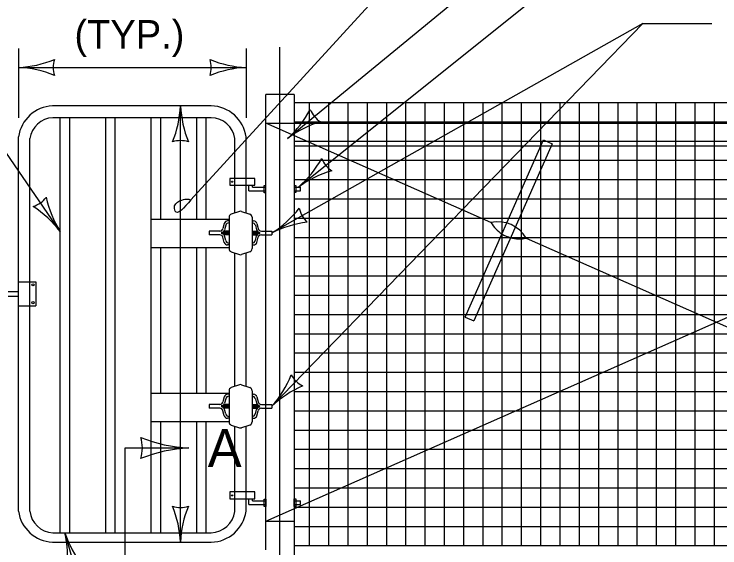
# Model space of a CAD drawing. Extents: x 49991.4 to 50021, y 49987.6 to 50011.4.
# Drawn here: x 50002.451 to 50003.939, y 49989.872 to 49990.998 of the extents above; entities that cross this region are included whole.
import ezdxf

# ---------------------------------------------------------------- set-up
doc = ezdxf.new("R2010")
doc.units = 0
for name, color, linetype in [('Level 1', 7, 'Continuous'), ('Level 2', 7, 'Continuous'), ('Level 3', 7, 'Continuous'), ('Level 4', 7, 'Continuous'), ('Level 5', 7, 'Continuous'), ('Level 6', 7, 'Continuous')]:
    doc.layers.add(name, color=color, linetype=linetype)

msp = doc.modelspace()

# ---------------------------------------------------------------- linework, layer by layer
at = {"layer": 'Level 1'}
for p, q in [((50003.0415, 49990.8281), (50002.9815, 49990.8281)), ((50002.9815, 49990.5402), (50002.9815, 49990.8281)), ((50003.0415, 49990.8281), (50003.0415, 49989.8078)), ((50004.8216, 49990.8107), (50003.0415, 49990.8107)), ((50003.074, 49989.8759), (50003.074, 49990.8107)), ((50003.1146, 49989.8759), (50003.1146, 49990.8107)), ((50003.1553, 49989.8759), (50003.1553, 49990.8107)), ((50003.1959, 49989.8759), (50003.1959, 49990.8107)), ((50003.2366, 49989.8759), (50003.2366, 49990.8107)), ((50003.2772, 49989.8759), (50003.2772, 49990.8107)), ((50003.3178, 49989.8759), (50003.3178, 49990.8107)), ((50003.3585, 49989.8759), (50003.3585, 49990.8107)), ((50003.3991, 49989.8759), (50003.3991, 49990.8107)), ((50003.4398, 49989.8759), (50003.4398, 49990.8107)), ((50003.4804, 49989.8759), (50003.4804, 49990.8107)), ((50003.5211, 49989.8759), (50003.5211, 49990.8107)), ((50003.5617, 49989.8759), (50003.5617, 49990.8107)), ((50003.6023, 49989.8759), (50003.6023, 49990.8107)), ((50003.643, 49989.8759), (50003.643, 49990.8107)), ((50003.6836, 49989.8759), (50003.6836, 49990.8107)), ((50003.7243, 49989.8759), (50003.7243, 49990.8107)), ((50003.7649, 49989.8759), (50003.7649, 49990.8107)), ((50003.8055, 49989.8759), (50003.8055, 49990.8107)), ((50003.8462, 49989.8759), (50003.8462, 49990.8107)), ((50003.8868, 49989.8759), (50003.8868, 49990.8107)), ((50003.9275, 49989.8759), (50003.9275, 49990.8107)), ((50002.8667, 49990.8044), (50002.532, 49990.8044)), ((50002.8669, 49990.7794), (50002.5324, 49990.7794)), ((50002.5483, 49989.9038), (50002.5483, 49990.7794)), ((50002.5683, 49989.9038), (50002.5683, 49990.7794)), ((50002.6443, 49989.9038), (50002.6443, 49990.7794)), ((50002.6643, 49989.9038), (50002.6643, 49990.7794)), ((50002.7403, 49989.9038), (50002.7403, 49990.7794)), ((50002.7603, 49990.5652), (50002.7603, 49990.7794)), ((50002.8363, 49990.5652), (50002.8363, 49990.7794)), ((50002.8563, 49990.5652), (50002.8563, 49990.7794)), ((50002.9815, 49990.768), (50004.8216, 49990.768)), ((50003.4565, 49990.5582), (50002.9815, 49990.768)), ((50004.8216, 49990.77), (50003.0415, 49990.77)), ((50002.4602, 49989.9493), (50002.4602, 49990.7389)), ((50002.4842, 49989.9493), (50002.4842, 49990.7354)), ((50002.9162, 49990.5782), (50002.9162, 49990.7353)), ((50002.9402, 49990.5784), (50002.9402, 49990.7388)), ((50003.402, 49990.3588), (50003.5671, 49990.7324)), ((50003.5671, 49990.7324), (50003.5854, 49990.7243)), ((50004.8216, 49990.7294), (50003.0415, 49990.7294)), ((50003.0415, 49990.7201), (50004.8216, 49990.7201)), ((50003.5854, 49990.7243), (50003.4202, 49990.3507)), ((50004.8216, 49990.6888), (50003.0415, 49990.6888)), ((50002.9057, 49990.6514), (50002.9057, 49990.6367)), ((50002.9588, 49990.6514), (50002.9057, 49990.6514)), ((50002.9588, 49990.6367), (50002.9588, 49990.6514)), ((50004.8216, 49990.6481), (50003.0415, 49990.6481)), ((50002.9057, 49990.6367), (50002.9588, 49990.6367)), ((50002.9461, 49990.6253), (50002.9461, 49990.6367)), ((50002.9537, 49990.6328), (50002.9537, 49990.6367)), ((50002.9537, 49990.6328), (50002.9815, 49990.6328)), ((50002.978, 49990.621), (50002.978, 49990.6365)), ((50002.978, 49990.6365), (50002.9815, 49990.6365)), ((50003.0415, 49990.6366), (50003.045, 49990.6366)), ((50003.0416, 49990.6328), (50003.055, 49990.6328)), ((50003.045, 49990.6366), (50003.045, 49990.6212)), ((50003.055, 49990.6253), (50003.055, 49990.6328)), ((50002.9461, 49990.6253), (50002.9815, 49990.6253)), ((50002.9815, 49990.621), (50002.978, 49990.621)), ((50003.0415, 49990.6253), (50003.055, 49990.6253)), ((50003.045, 49990.6212), (50003.0415, 49990.6212)), ((50004.8216, 49990.6075), (50003.0415, 49990.6075)), ((50002.9042, 49990.5692), (50002.9042, 49990.5031)), ((50002.9263, 49990.5815), (50002.909, 49990.5758)), ((50002.9307, 49990.5815), (50002.948, 49990.5758)), ((50002.9528, 49990.5692), (50002.9528, 49990.5031)), ((50002.7403, 49990.5652), (50002.9042, 49990.5652)), ((50002.8942, 49990.5563), (50002.8913, 49990.5453)), ((50002.9042, 49990.5615), (50002.901, 49990.5615)), ((50002.9042, 49990.5575), (50002.904, 49990.5575)), ((50002.9528, 49990.5615), (50002.956, 49990.5615)), ((50002.9528, 49990.5575), (50002.9529, 49990.5575)), ((50002.9628, 49990.5563), (50002.9657, 49990.5453)), ((50004.8216, 49990.5668), (50003.0415, 49990.5668)), ((50002.8625, 49990.5402), (50002.8625, 49990.5322)), ((50002.8845, 49990.5402), (50002.8625, 49990.5402)), ((50002.9042, 49990.5402), (50002.8935, 49990.5402)), ((50002.8973, 49990.5523), (50002.8947, 49990.5425)), ((50002.9528, 49990.5402), (50002.9635, 49990.5402)), ((50002.9597, 49990.5523), (50002.9623, 49990.5425)), ((50002.9724, 49990.5402), (50002.9945, 49990.5402)), ((50002.9815, 49990.5322), (50002.9815, 49990.5402)), ((50002.9945, 49990.5402), (50002.9945, 49990.5322)), ((50002.8845, 49990.5322), (50002.8625, 49990.5322)), ((50002.9042, 49990.5374), (50002.8879, 49990.5374)), ((50002.9042, 49990.535), (50002.8879, 49990.535)), ((50002.8942, 49990.516), (50002.8913, 49990.527)), ((50002.9042, 49990.5322), (50002.8935, 49990.5322)), ((50002.8973, 49990.52), (50002.8947, 49990.5298)), ((50002.9528, 49990.5374), (50002.9691, 49990.5374)), ((50002.9528, 49990.535), (50002.9691, 49990.535)), ((50002.9528, 49990.5322), (50002.9635, 49990.5322)), ((50002.9597, 49990.52), (50002.9623, 49990.5298)), ((50002.9628, 49990.516), (50002.9657, 49990.527)), ((50002.9724, 49990.5322), (50002.9945, 49990.5322)), ((50002.9815, 49990.1745), (50002.9815, 49990.5322)), ((50002.9815, 49989.928), (50004.3322, 49990.5251)), ((50004.8216, 49990.5262), (50003.0415, 49990.5262)), ((50003.5309, 49990.5253), (50004.8816, 49989.9281)), ((50002.9042, 49990.5109), (50002.901, 49990.5109)), ((50002.9042, 49990.5149), (50002.904, 49990.5149)), ((50002.9528, 49990.5149), (50002.9529, 49990.5149)), ((50002.9528, 49990.5109), (50002.956, 49990.5109)), ((50002.7403, 49990.5052), (50002.9042, 49990.5052)), ((50002.7603, 49990.1982), (50002.7603, 49990.5052)), ((50002.8363, 49990.1982), (50002.8363, 49990.5052)), ((50002.8563, 49990.1982), (50002.8563, 49990.5052)), ((50002.909, 49990.4965), (50002.9263, 49990.4908)), ((50002.9162, 49990.2126), (50002.9162, 49990.4941)), ((50002.948, 49990.4965), (50002.9307, 49990.4908)), ((50002.9402, 49990.2127), (50002.9402, 49990.4939)), ((50004.8216, 49990.4855), (50003.0415, 49990.4855)), ((50004.8216, 49990.4449), (50003.0415, 49990.4449)), ((50002.4602, 49990.4332), (50002.4967, 49990.4332)), ((50002.4967, 49990.4332), (50002.4967, 49990.3824)), ((50002.4389, 49990.4128), (50002.4602, 49990.4128)), ((50002.4389, 49990.4028), (50002.4602, 49990.4028)), ((50004.8216, 49990.4043), (50003.0415, 49990.4043)), ((50002.4602, 49990.3824), (50002.4967, 49990.3824)), ((50004.8216, 49990.3636), (50003.0415, 49990.3636)), ((50003.402, 49990.3588), (50003.4202, 49990.3507)), ((50004.8216, 49990.323), (50003.0415, 49990.323)), ((50004.8216, 49990.2823), (50003.0415, 49990.2823)), ((50004.8216, 49990.2417), (50003.0415, 49990.2417)), ((50002.9263, 49990.2159), (50002.909, 49990.2102)), ((50002.9307, 49990.2159), (50002.948, 49990.2102)), ((50002.7403, 49990.1982), (50002.9042, 49990.1982)), ((50002.9042, 49990.2035), (50002.9042, 49990.1375)), ((50002.9528, 49990.2035), (50002.9528, 49990.1375)), ((50004.8216, 49990.201), (50003.0415, 49990.201)), ((50002.8942, 49990.1906), (50002.8913, 49990.1797)), ((50002.8973, 49990.1866), (50002.8947, 49990.1769)), ((50002.9042, 49990.1958), (50002.901, 49990.1958)), ((50002.9042, 49990.1918), (50002.904, 49990.1918)), ((50002.9528, 49990.1958), (50002.956, 49990.1958)), ((50002.9528, 49990.1918), (50002.9529, 49990.1918)), ((50002.9597, 49990.1866), (50002.9623, 49990.1769)), ((50002.9628, 49990.1906), (50002.9657, 49990.1797)), ((50002.8625, 49990.1745), (50002.8625, 49990.1665)), ((50002.8845, 49990.1745), (50002.8625, 49990.1745)), ((50002.9042, 49990.1717), (50002.8879, 49990.1717)), ((50002.9042, 49990.1693), (50002.8879, 49990.1693)), ((50002.9042, 49990.1745), (50002.8935, 49990.1745)), ((50002.9528, 49990.1745), (50002.9635, 49990.1745)), ((50002.9528, 49990.1717), (50002.9691, 49990.1717)), ((50002.9528, 49990.1693), (50002.9691, 49990.1693)), ((50002.9724, 49990.1745), (50002.9945, 49990.1745)), ((50002.9815, 49990.1665), (50002.9815, 49990.1745)), ((50002.9945, 49990.1745), (50002.9945, 49990.1665)), ((50002.8845, 49990.1665), (50002.8625, 49990.1665)), ((50002.8942, 49990.1504), (50002.8913, 49990.1613)), ((50002.9042, 49990.1665), (50002.8935, 49990.1665)), ((50002.8973, 49990.1544), (50002.8947, 49990.1641)), ((50002.9528, 49990.1665), (50002.9635, 49990.1665)), ((50002.9597, 49990.1544), (50002.9623, 49990.1641)), ((50002.9628, 49990.1504), (50002.9657, 49990.1613)), ((50002.9724, 49990.1665), (50002.9945, 49990.1665)), ((50002.9815, 49989.8678), (50002.9815, 49990.1665)), ((50004.8216, 49990.1604), (50003.0415, 49990.1604)), ((50002.7403, 49990.1382), (50002.9042, 49990.1382)), ((50002.7603, 49989.9038), (50002.7603, 49990.1382)), ((50002.8363, 49989.9038), (50002.8363, 49990.1382)), ((50002.8563, 49989.9038), (50002.8563, 49990.1382)), ((50002.9042, 49990.1452), (50002.901, 49990.1452)), ((50002.9042, 49990.1492), (50002.904, 49990.1492)), ((50002.9528, 49990.1492), (50002.9529, 49990.1492)), ((50002.9528, 49990.1452), (50002.956, 49990.1452)), ((50002.909, 49990.1308), (50002.9263, 49990.1251)), ((50002.9162, 49989.9488), (50002.9162, 49990.1284)), ((50002.948, 49990.1308), (50002.9307, 49990.1251)), ((50002.9402, 49989.9494), (50002.9402, 49990.1282)), ((50004.8216, 49990.1198), (50003.0415, 49990.1198)), ((50004.8216, 49990.0791), (50003.0415, 49990.0791)), ((50004.8216, 49990.0385), (50003.0415, 49990.0385)), ((50004.8216, 49989.9978), (50003.0415, 49989.9978)), ((50002.9461, 49989.9636), (50002.9461, 49989.9751)), ((50002.9537, 49989.9712), (50002.9537, 49989.9751)), ((50002.9461, 49989.9636), (50002.9815, 49989.9636)), ((50002.9537, 49989.9712), (50002.9815, 49989.9712)), ((50003.0415, 49989.9712), (50003.055, 49989.9712)), ((50003.0415, 49989.9636), (50003.055, 49989.9636)), ((50003.055, 49989.9636), (50003.055, 49989.9712)), ((50004.8216, 49989.9572), (50003.0415, 49989.9572)), ((50002.9815, 49989.928), (50003.0415, 49989.928)), ((50004.8216, 49989.9166), (50003.0415, 49989.9166)), ((50002.5324, 49989.9038), (50002.8667, 49989.9038)), ((50002.5319, 49989.8838), (50002.8667, 49989.8838)), ((50004.8216, 49989.8759), (50003.0415, 49989.8759))]:
    msp.add_line(p, q, dxfattribs=at)
for points in [[(50002.9588, 49989.9751), (50002.9588, 49989.9898), (50002.9057, 49989.9898), (50002.9057, 49989.9751)], [(50002.9815, 49989.9748), (50002.9815, 49989.9594), (50002.978, 49989.9594), (50002.978, 49989.9748)], [(50003.045, 49989.975), (50003.045, 49989.9595), (50003.0415, 49989.9595), (50003.0415, 49989.975)]]:
    msp.add_lwpolyline(points, close=True, dxfattribs=at)
for centre, radius in [((50002.9108, 49990.6443), 0.00125), ((50002.4909, 49990.4269), 0.00227), ((50002.4909, 49990.389), 0.00227), ((50002.9108, 49989.9827), 0.00125)]:
    msp.add_circle(centre, radius, dxfattribs=at)
for centre, radius, start, end in [((50002.5357, 49990.7283), 0.0762, 92.7377, 171.9677), ((50002.8647, 49990.7282), 0.0762, 8.0258, 88.4771), ((50002.5349, 49990.7282), 0.0512, 92.7386, 171.9742), ((50002.8655, 49990.7282), 0.0512, 8.0258, 88.4771), ((50002.9112, 49990.5692), 0.007, 108.219, 180), ((50002.9285, 49990.5749), 0.007, 71.7915, 108.219), ((50002.9458, 49990.5692), 0.007, 0, 71.7915), ((50002.901, 49990.5545), 0.007, 90, 165), ((50002.904, 49990.5505), 0.007, 88.8157, 165), ((50002.9529, 49990.5505), 0.007, 15, 90), ((50002.956, 49990.5545), 0.007, 15, 90), ((50003.4709, 49990.4903), 0.0694, 30.2241, 102.0148), ((50003.5164, 49990.5932), 0.0694, 210.2884, 237.9426), ((50002.8845, 49990.5472), 0.007, 270, 345), ((50002.8879, 49990.5444), 0.007, 270, 345), ((50002.9691, 49990.5444), 0.007, 195, 270), ((50002.9724, 49990.5472), 0.007, 195, 270), ((50002.8845, 49990.5252), 0.007, 15, 90), ((50002.8879, 49990.528), 0.007, 15, 90), ((50002.9691, 49990.528), 0.007, 90, 165), ((50002.9724, 49990.5252), 0.007, 90, 165), ((50003.5165, 49990.5931), 0.0694, 254.4342, 281.9719), ((50002.901, 49990.5179), 0.007, 195, 270), ((50002.904, 49990.5219), 0.007, 195, 271.1843), ((50002.9529, 49990.5219), 0.007, 270, 345), ((50002.956, 49990.5179), 0.007, 270, 345), ((50002.9112, 49990.5031), 0.007, 180, 251.781), ((50002.9458, 49990.5031), 0.007, 288.2085, 360), ((50002.9285, 49990.4974), 0.007, 251.781, 288.2085), ((50002.9285, 49990.2092), 0.007, 71.7915, 108.219), ((50002.9112, 49990.2035), 0.007, 108.219, 180), ((50002.9458, 49990.2035), 0.007, 0, 71.7915), ((50002.901, 49990.1888), 0.007, 90, 165), ((50002.904, 49990.1848), 0.007, 90, 165), ((50002.9529, 49990.1848), 0.007, 15, 91.0609), ((50002.956, 49990.1888), 0.007, 15, 90), ((50002.8845, 49990.1815), 0.007, 270, 345), ((50002.8879, 49990.1787), 0.007, 270, 345), ((50002.8879, 49990.1623), 0.007, 15, 90), ((50002.9691, 49990.1787), 0.007, 195, 270.0155), ((50002.9691, 49990.1623), 0.007, 90, 165), ((50002.9724, 49990.1815), 0.007, 195, 270), ((50002.8845, 49990.1595), 0.007, 15, 90), ((50002.904, 49990.1562), 0.007, 195, 271.1843), ((50002.9529, 49990.1562), 0.007, 270, 345), ((50002.9724, 49990.1595), 0.007, 90, 165), ((50002.901, 49990.1522), 0.007, 195, 270), ((50002.9112, 49990.1375), 0.007, 180, 251.781), ((50002.9458, 49990.1375), 0.007, 288.2085, 360), ((50002.956, 49990.1522), 0.007, 270, 345), ((50002.9285, 49990.1318), 0.007, 251.781, 288.2085), ((50002.5356, 49989.9599), 0.0761, 187.9724, 267.208), ((50002.5358, 49989.9557), 0.052, 187.0581, 266.2937), ((50002.8647, 49989.96), 0.0762, 271.5229, 351.9742), ((50002.8654, 49989.955), 0.0512, 271.5229, 353.0872)]:
    msp.add_arc(centre, radius, start, end, dxfattribs=at)
at = {"layer": 'Level 3'}
for p, q in [((50002.8237, 49990.6059), (50003.6297, 49991.4876)), ((50003.0273, 49990.7353), (50003.7765, 49991.3512)), ((50002.5482, 49990.5392), (50002.0589, 49991.2474)), ((50003.0509, 49990.6328), (50003.7765, 49991.2147)), ((50003.7765, 49990.9783), (50002.9945, 49990.5362)), ((50003.7765, 49990.9783), (50002.9945, 49990.1705)), ((50003.7765, 49990.9783), (50003.9219, 49990.9783)), ((50002.4602, 49990.9253), (50002.4602, 49990.7789)), ((50002.9402, 49990.9254), (50002.9402, 49990.7789)), ((50002.4602, 49990.8853), (50002.9402, 49990.8853)), ((50002.8019, 49989.8838), (50002.8019, 49990.8044)), ((50002.558, 49989.9038), (50002.765, 49989.1673))]:
    msp.add_line(p, q, dxfattribs=at)
for centre, radius, start, end in [((50002.4487, 49991.118), 0.233, 272.8273, 292.0772), ((50002.5884, 49990.8853), 0.0548, 162.1388, 197.8612), ((50002.9494, 49991.1074), 0.2223, 247.456, 267.6395), ((50002.812, 49990.8853), 0.0548, 342.1388, 17.8612), ((50002.451, 49990.6632), 0.2223, 67.456, 87.6395), ((50002.9517, 49990.6526), 0.233, 92.8273, 112.0772), ((50002.5797, 49990.8135), 0.2223, 337.456, 357.6395), ((50003.0346, 49990.8159), 0.233, 182.8273, 202.0772), ((50002.8707, 49990.9077), 0.233, 312.2491, 331.499), ((50003.1264, 49990.8167), 0.0548, 201.5607, 237.283), ((50003.1613, 49990.5579), 0.2223, 106.8778, 127.0614), ((50002.8019, 49990.6762), 0.0548, 72.1388, 107.8612), ((50002.8963, 49990.8072), 0.233, 311.5553, 330.8052), ((50003.1509, 49990.713), 0.0548, 200.8668, 236.5892), ((50003.1827, 49990.4538), 0.2223, 106.184, 126.3675), ((50002.4754, 49990.6447), 0.0548, 286.7815, 322.5039), ((50002.7362, 49990.658), 0.2223, 192.0987, 212.2822), ((50002.3633, 49990.3975), 0.233, 37.47, 56.7199), ((50002.8699, 49990.7331), 0.233, 302.31, 321.5599), ((50003.1061, 49990.5993), 0.0548, 191.6215, 227.3439), ((50003.0958, 49990.3383), 0.2223, 96.9387, 117.1222), ((50002.8193, 49990.3241), 0.233, 318.756, 338.0059), ((50003.0836, 49990.2626), 0.0548, 208.0675, 243.7899), ((50003.1477, 49990.0094), 0.2223, 113.3847, 133.5682), ((50002.8316, 49990.3788), 0.2964, 247.456, 267.6395), ((50002.6485, 49990.0826), 0.073, 342.1388, 17.8612), ((50002.8347, 49989.7723), 0.3107, 92.8273, 112.0772), ((50002.8019, 49990.012), 0.0548, 252.1388, 287.8612), ((50002.5692, 49989.8723), 0.233, 2.8273, 22.0772), ((50003.024, 49989.8747), 0.2223, 157.456, 177.6395), ((50002.3416, 49989.8525), 0.2223, 353.155, 13.3385), ((50002.7789, 49989.9779), 0.233, 198.5263, 217.7761)]:
    msp.add_arc(centre, radius, start, end, dxfattribs=at)
msp.add_spline([(50002.8237, 49990.6059), (50002.7906, 49990.5825), (50002.7896, 49990.5936), (50002.8047, 49990.6056), (50002.8178, 49990.6076), (50002.8239, 49990.6056)], degree=3, dxfattribs=at)
at = {"layer": 'Level 4'}
msp.add_arc((50003.5165, 49990.5931), 0.0694, 237.8573, 254.4342, dxfattribs=at)
at = {"layer": 'Level 5'}
msp.add_line((50003.0115, 49989.2638), (50003.0115, 49990.9281), dxfattribs=at)
at = {"layer": 'Level 6'}
for p, q in [((50002.6855, 49990.0826), (50002.8194, 49990.0826)), ((50002.6855, 49989.6856), (50002.6855, 49990.0826))]:
    msp.add_line(p, q, dxfattribs=at)

# ---------------------------------------------------------------- texts
at = {"layer": 'Level 2'}
for s, height, p in [('(TYP.)', 0.06, (50002.5783, 49990.9253)), ('A', 0.08, (50002.8594, 49990.0426))]:
    msp.add_text(s, height=height, dxfattribs=at).set_placement(p)

doc.saveas('drawing.dxf')
